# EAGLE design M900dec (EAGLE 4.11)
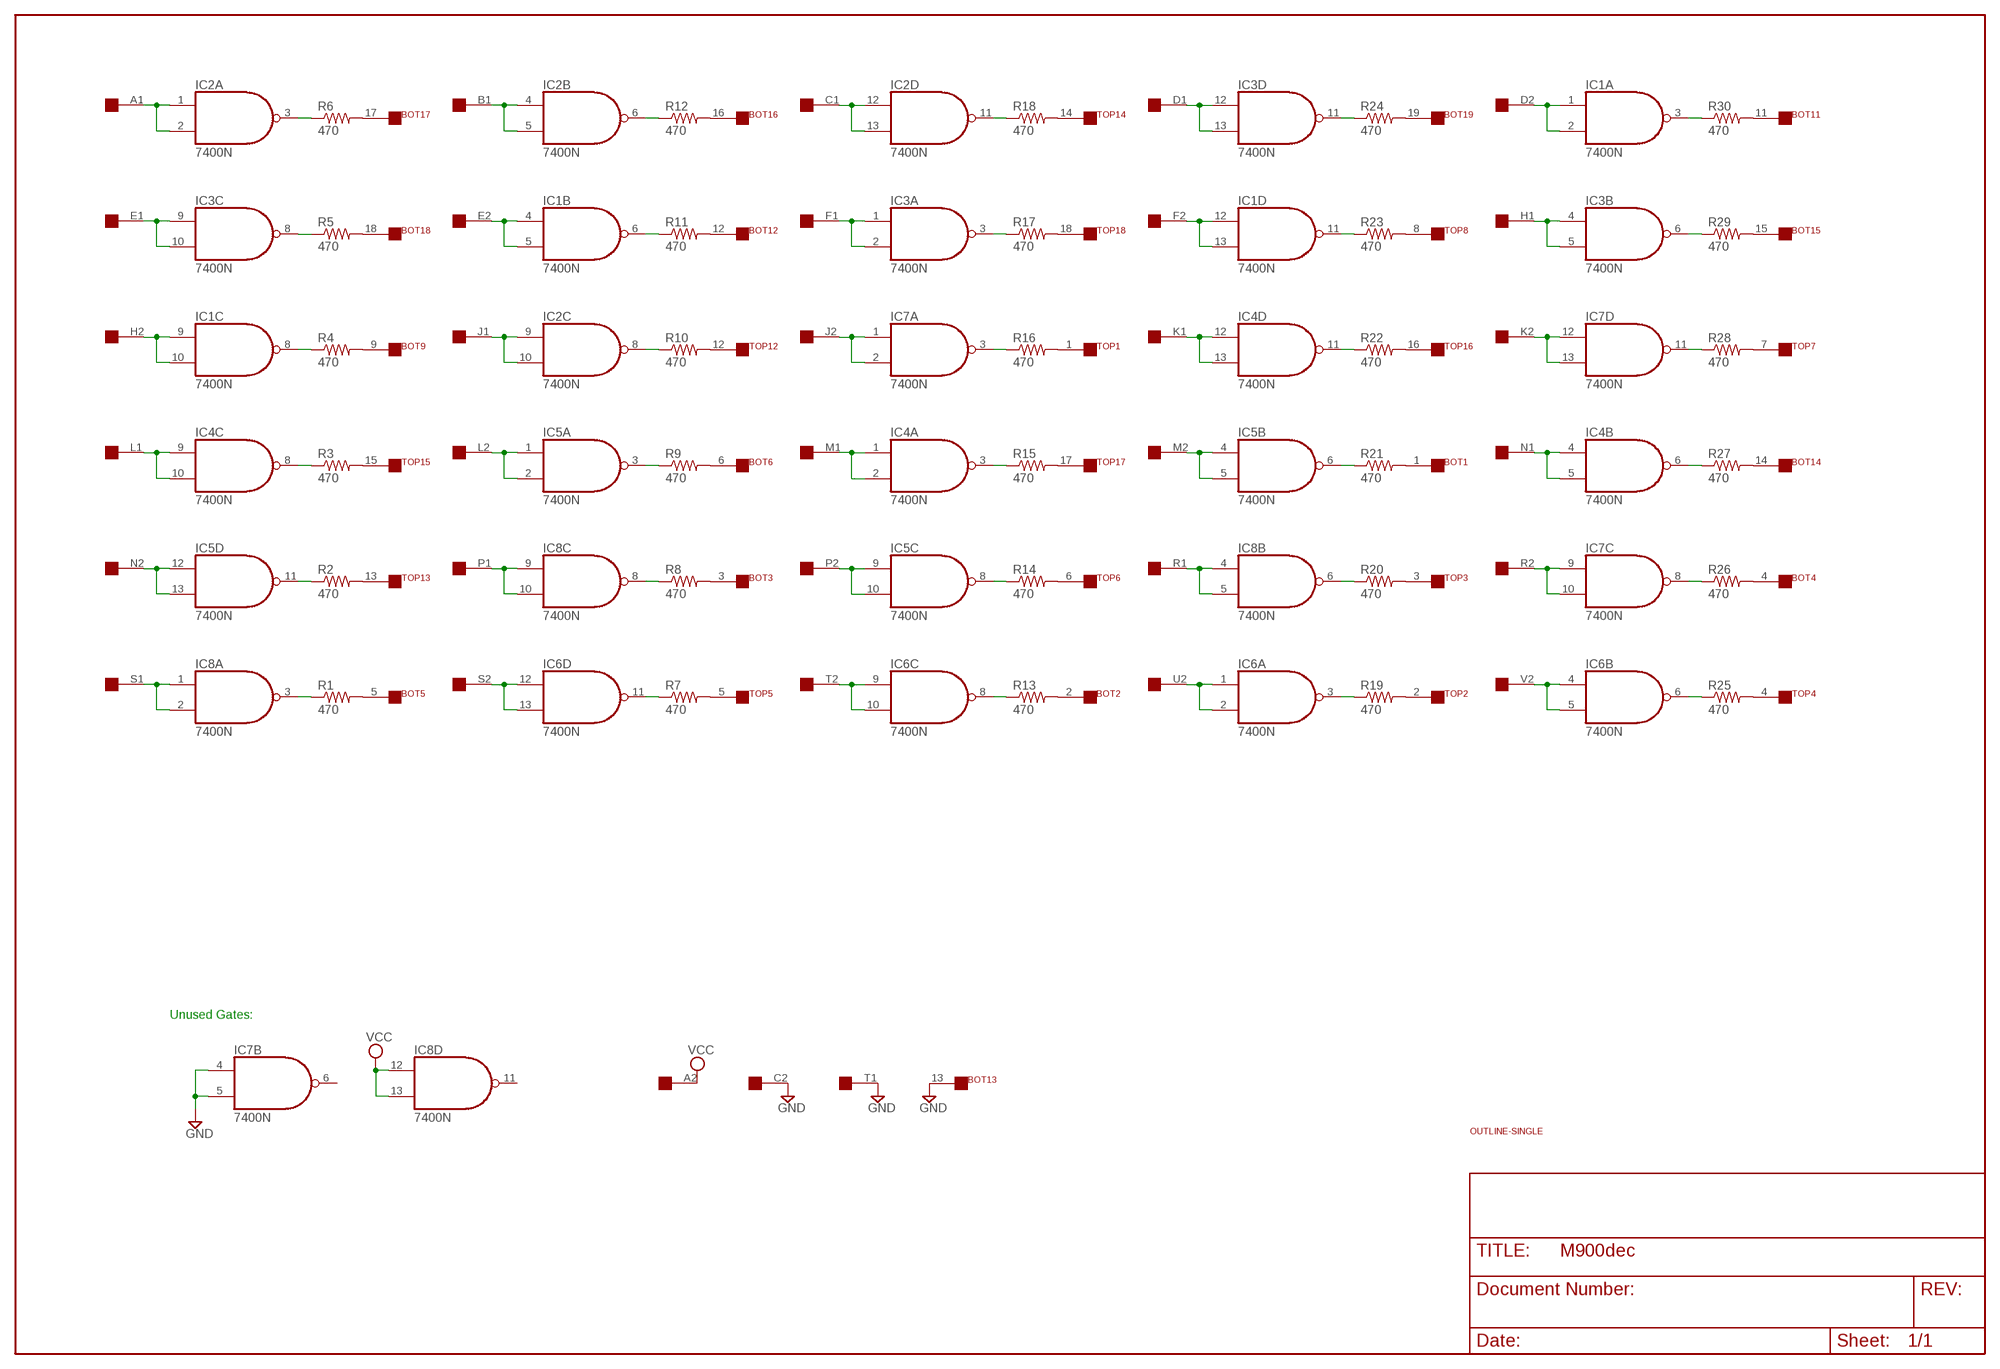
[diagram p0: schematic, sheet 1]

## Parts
BOT  FLEX19  [FLEX19]
EDGE  SINGLE  [EDGE-CON2]
IC1  7400N  [DIL14]
IC2  7400N  [DIL14]
IC3  7400N  [DIL14]
IC4  7400N  [DIL14]
IC5  7400N  [DIL14]
IC6  7400N  [DIL14]
IC7  7400N  [DIL14]
IC8  7400N  [DIL14]
R1  470  R-US_0207/10  [0207/10]
R2  470  R-US_0207/10  [0207/10]
R3  470  R-US_0207/10  [0207/10]
R4  470  R-US_0207/10  [0207/10]
R5  470  R-US_0207/10  [0207/10]
R6  470  R-US_0207/10  [0207/10]
R7  470  R-US_0207/10  [0207/10]
R8  470  R-US_0207/10  [0207/10]
R9  470  R-US_0207/10  [0207/10]
R10  470  R-US_0207/10  [0207/10]
R11  470  R-US_0207/10  [0207/10]
R12  470  R-US_0207/10  [0207/10]
R13  470  R-US_0207/10  [0207/10]
R14  470  R-US_0207/10  [0207/10]
R15  470  R-US_0207/10  [0207/10]
R16  470  R-US_0207/10  [0207/10]
R17  470  R-US_0207/10  [0207/10]
R18  470  R-US_0207/10  [0207/10]
R19  470  R-US_0207/10  [0207/10]
R20  470  R-US_0207/10  [0207/10]
R21  470  R-US_0207/10  [0207/10]
R22  470  R-US_0207/10  [0207/10]
R23  470  R-US_0207/10  [0207/10]
R24  470  R-US_0207/10  [0207/10]
R25  470  R-US_0207/10  [0207/10]
R26  470  R-US_0207/10  [0207/10]
R27  470  R-US_0207/10  [0207/10]
R28  470  R-US_0207/10  [0207/10]
R29  470  R-US_0207/10  [0207/10]
R30  470  R-US_0207/10  [0207/10]
TOP  FLEX19  [FLEX19]
U$2  OUTLINE-SINGLE  [SINGLE]

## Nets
GND: BOT.13 EDGE.C2 EDGE.T1 IC7.4(B:I0) IC7.5(B:I1)
N$1: EDGE.A1 IC2.1(A:I0) IC2.2(A:I1)
N$2: IC2.3(A:O) R6.1
N$3: IC3.8(C:O) R5.1
N$4: IC1.8(C:O) R4.1
N$5: IC4.8(C:O) R3.1
N$6: IC5.11(D:O) R2.1
N$7: EDGE.H2 IC1.9(C:I0) IC1.10(C:I1)
N$8: EDGE.S1 IC8.1(A:I0) IC8.2(A:I1)
N$9: EDGE.N2 IC5.12(D:I0) IC5.13(D:I1)
N$10: EDGE.L1 IC4.9(C:I0) IC4.10(C:I1)
N$11: EDGE.E1 IC3.9(C:I0) IC3.10(C:I1)
N$12: EDGE.P1 IC8.9(C:I0) IC8.10(C:I1)
N$13: EDGE.B1 IC2.4(B:I0) IC2.5(B:I1)
N$14: EDGE.E2 IC1.4(B:I0) IC1.5(B:I1)
N$15: EDGE.J1 IC2.9(C:I0) IC2.10(C:I1)
N$16: EDGE.L2 IC5.1(A:I0) IC5.2(A:I1)
N$17: EDGE.S2 IC6.12(D:I0) IC6.13(D:I1)
N$18: IC8.8(C:O) R8.1
N$19: IC5.3(A:O) R9.1
N$20: IC2.8(C:O) R10.1
N$21: IC1.6(B:O) R11.1
N$22: IC2.6(B:O) R12.1
N$23: IC6.11(D:O) R7.1
N$24: IC8.3(A:O) R1.1
N$25: EDGE.P2 IC5.9(C:I0) IC5.10(C:I1)
N$26: EDGE.C1 IC2.12(D:I0) IC2.13(D:I1)
N$27: EDGE.F1 IC3.1(A:I0) IC3.2(A:I1)
N$28: EDGE.J2 IC7.1(A:I0) IC7.2(A:I1)
N$29: EDGE.M1 IC4.1(A:I0) IC4.2(A:I1)
N$30: EDGE.T2 IC6.9(C:I0) IC6.10(C:I1)
N$31: IC6.8(C:O) R13.1
N$32: IC5.8(C:O) R14.1
N$33: IC4.3(A:O) R15.1
N$34: IC7.3(A:O) R16.1
N$35: IC2.11(D:O) R18.1
N$36: IC3.3(A:O) R17.1
N$37: IC6.3(A:O) R19.1
N$38: IC8.6(B:O) R20.1
N$39: IC5.6(B:O) R21.1
N$40: IC4.11(D:O) R22.1
N$41: IC1.11(D:O) R23.1
N$42: IC3.11(D:O) R24.1
N$43: EDGE.R1 IC8.4(B:I0) IC8.5(B:I1)
N$44: EDGE.F2 IC1.12(D:I0) IC1.13(D:I1)
N$45: EDGE.K1 IC4.12(D:I0) IC4.13(D:I1)
N$46: EDGE.M2 IC5.4(B:I0) IC5.5(B:I1)
N$47: EDGE.U2 IC6.1(A:I0) IC6.2(A:I1)
N$48: EDGE.R2 IC7.9(C:I0) IC7.10(C:I1)
N$49: EDGE.D1 IC3.12(D:I0) IC3.13(D:I1)
N$50: EDGE.D2 IC1.1(A:I0) IC1.2(A:I1)
N$51: EDGE.H1 IC3.4(B:I0) IC3.5(B:I1)
N$52: EDGE.K2 IC7.12(D:I0) IC7.13(D:I1)
N$53: EDGE.N1 IC4.4(B:I0) IC4.5(B:I1)
N$54: EDGE.V2 IC6.4(B:I0) IC6.5(B:I1)
N$55: IC6.6(B:O) R25.1
N$56: IC7.8(C:O) R26.1
N$57: IC4.6(B:O) R27.1
N$58: IC7.11(D:O) R28.1
N$59: IC3.6(B:O) R29.1
N$60: IC1.3(A:O) R30.1
N$61: R17.2 TOP.18
N$62: R15.2 TOP.17
N$63: R22.2 TOP.16
N$64: R3.2 TOP.15
N$65: R18.2 TOP.14
N$66: R2.2 TOP.13
N$67: R10.2 TOP.12
N$68: R23.2 TOP.8
N$69: R28.2 TOP.7
N$70: R14.2 TOP.6
N$71: R7.2 TOP.5
N$72: R25.2 TOP.4
N$73: R20.2 TOP.3
N$74: R19.2 TOP.2
N$75: R16.2 TOP.1
N$76: BOT.15 R29.2
N$77: BOT.3 R8.2
N$78: BOT.1 R21.2
N$79: BOT.2 R13.2
N$80: BOT.4 R26.2
N$81: BOT.5 R1.2
N$82: BOT.19 R24.2
N$83: BOT.18 R5.2
N$84: BOT.17 R6.2
N$85: BOT.16 R12.2
N$86: BOT.14 R27.2
N$87: BOT.12 R11.2
N$88: BOT.9 R4.2
N$89: BOT.6 R9.2
N$90: BOT.11 R30.2
VCC: EDGE.A2 IC8.12(D:I0) IC8.13(D:I1)
Unconnected: BOT.7 BOT.8 BOT.10 EDGE.B2 EDGE.U1 EDGE.V1 IC7.6(B:O) IC8.11(D:O) TOP.9 TOP.10 TOP.11 TOP.19

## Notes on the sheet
- Unused Gates:

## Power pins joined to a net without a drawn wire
GND: IC1.7(P:GND) IC2.7(P:GND) IC3.7(P:GND) IC4.7(P:GND) IC5.7(P:GND) IC6.7(P:GND) IC7.7(P:GND) IC8.7(P:GND)
VCC: IC1.14(P:VCC) IC2.14(P:VCC) IC3.14(P:VCC) IC4.14(P:VCC) IC5.14(P:VCC) IC6.14(P:VCC) IC7.14(P:VCC) IC8.14(P:VCC)

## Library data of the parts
BOT TOP = dec-con:FLEX19
EDGE = dec-con:SINGLE: Single-Height DEC board
IC1-IC8 = 74xx-jameco:74*00: Quad 2-input NAND gate
R1-R30 = rcl:R-US_: RESISTOR, American symbol
U$2 = dec-con:OUTLINE-*: Board outlines for DEC boards.

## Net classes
1 Supply: width 0.762 mm

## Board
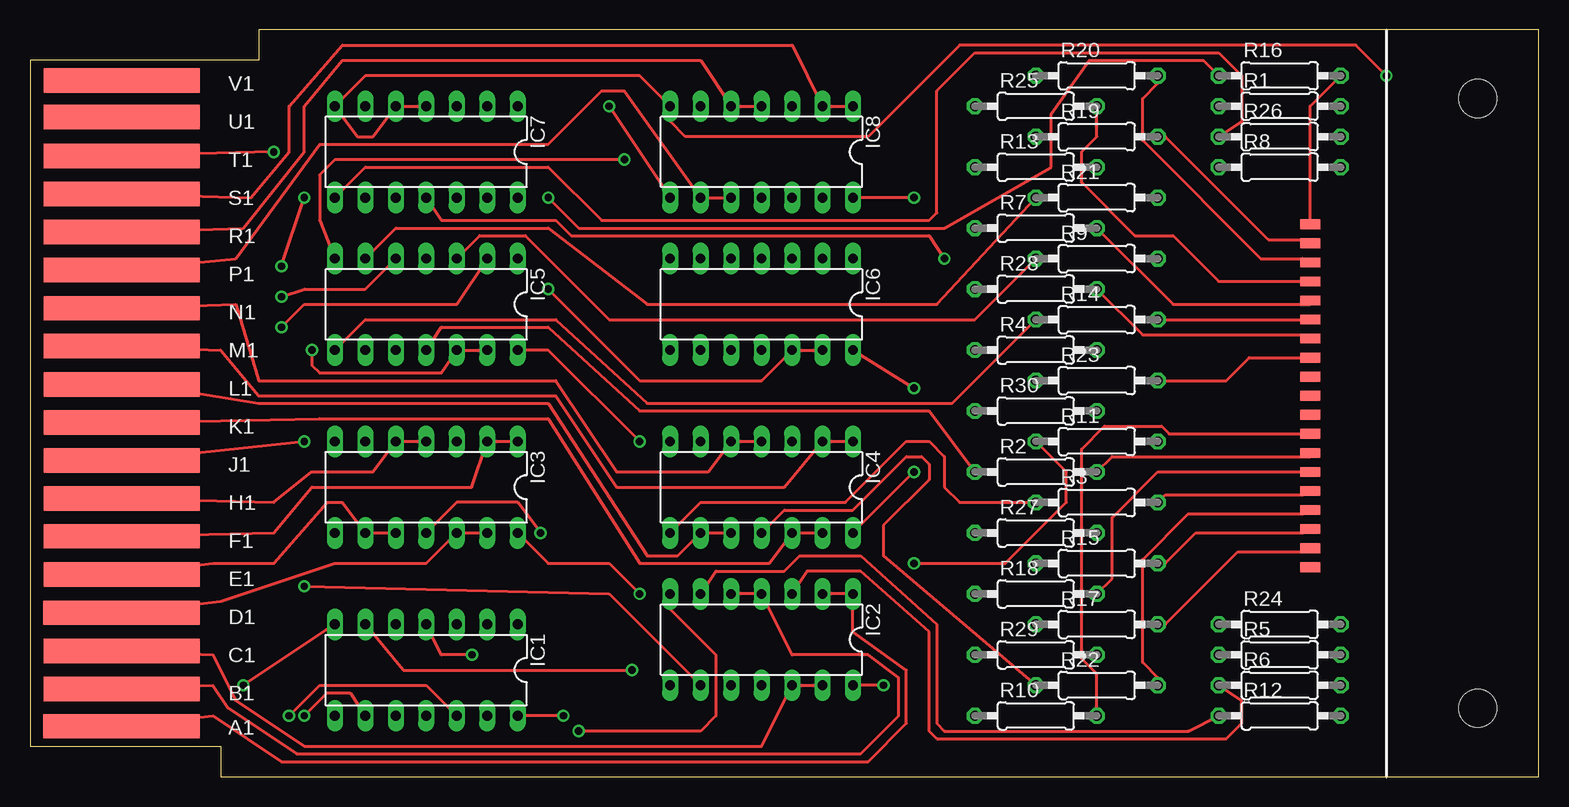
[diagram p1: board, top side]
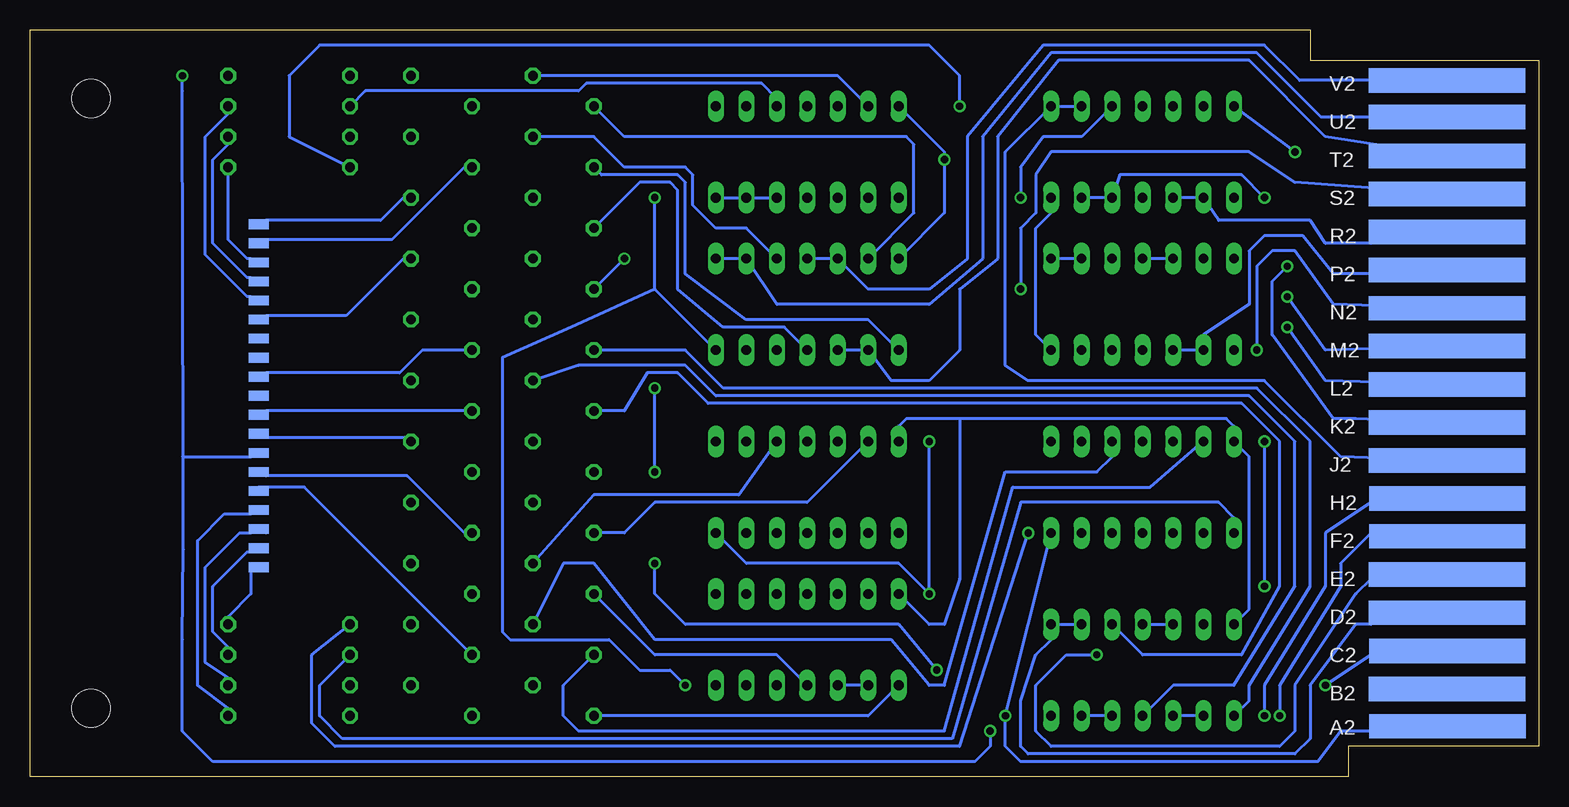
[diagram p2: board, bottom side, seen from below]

Size 125.73 x 62.23 mm. Coordinates in mm from the lower left corner, seen from the top.
Copper layers (1*16): Top 0.035mm / dielectric 1.5mm / Bottom 0.035mm
Design rules "10mils": minimum track width 10mil, minimum drill 24mil, track to track 10mil, track to pad 10mil, pad to pad 10mil, via to via 10mil, smd to smd 10mil, copper to edge 25mil, drill to drill 10mil, minimum pad ring 10mil, minimum via ring 8mil, stop-mask expansion 0mil, vias tented up to drill 0mil, thermal gap 10mil

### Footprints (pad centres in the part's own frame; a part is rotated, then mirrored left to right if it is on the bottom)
FLEX19 = smd 1.676 x 0.813: 1 0,14.287; 2 0,12.7; 3 0,11.113; 4 0,9.525; 5 0,7.938; 6 0,6.35; 7 0,4.763; 8 0,3.175; 9 0,1.587; 10 0,0; 11 0,-1.587; 12 0,-3.175; 13 0,-4.763; 14 0,-6.35; 15 0,-7.938; 16 0,-9.525; 17 0,-11.113; 18 0,-12.7; 19 0,-14.287
EDGE-CON2 = smd 13.017 x 2.032: A1 7.633,4.207; B1 7.639,7.327; C1 7.636,10.489; D1 7.633,13.665; E1 7.642,16.84; F1 7.642,20.041; H1 7.642,23.19; J1 7.642,26.34; K1 7.642,29.515; L1 7.642,32.69; M1 7.642,35.89; N1 7.642,39.04; P1 7.642,42.24; R1 7.642,45.39; S1 7.642,48.565; T1 7.642,51.74; U1 7.642,54.966; V1 7.642,58.026 | smd 13.017 x 2.032 bottom: A2 7.614,4.207; B2 7.642,7.328; C2 7.617,10.49; D2 7.642,13.665; E2 7.642,16.84; F2 7.617,20.041; H2 7.617,23.19; J2 7.642,26.34; K2 7.642,29.515; L2 7.642,32.69; M2 7.642,35.89; N2 7.642,39.04; P2 7.642,42.24; R2 7.642,45.39; S2 7.642,48.565; T2 7.642,51.74; U2 7.642,54.966; V2 7.642,58.026
DIL14 = drill 0.813 long: 1 -7.62,-3.81; 2 -5.08,-3.81; 3 -2.54,-3.81; 4 0,-3.81; 5 2.54,-3.81; 6 5.08,-3.81; 7 7.62,-3.81; 8 7.62,3.81; 9 5.08,3.81; 10 2.54,3.81; 11 0,3.81; 12 -2.54,3.81; 13 -5.08,3.81; 14 -7.62,3.81
0207/10 = drill 0.813 octagon: 1 -5.08,0; 2 5.08,0
SINGLE = hole 3.175: 120.65,56.515; 120.65,5.715

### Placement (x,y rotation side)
BOT  106.68,31.75 0 bottom
EDGE  0,0 0 top
IC1  33.02,8.89 180 top
IC2  60.96,11.43 180 top
IC3  33.02,24.13 180 top
IC4  60.96,24.13 180 top
IC5  33.02,39.37 180 top
IC6  60.96,39.37 180 top
IC7  33.02,52.07 180 top
IC8  60.96,52.07 180 top
R1  104.14,55.88 0 top
R2  83.82,25.4 0 top
R3  88.9,22.86 0 top
R4  83.82,35.56 0 top
R5  104.14,10.16 0 top
R6  104.14,7.62 0 top
R7  83.82,45.72 0 top
R8  104.14,50.8 0 top
R9  88.9,43.18 0 top
R10  83.82,5.08 0 top
R11  88.9,27.94 0 top
R12  104.14,5.08 0 top
R13  83.82,50.8 0 top
R14  88.9,38.1 0 top
R15  88.9,17.78 0 top
R16  104.14,58.42 0 top
R17  88.9,12.7 0 top
R18  83.82,15.24 0 top
R19  88.9,53.34 0 top
R20  88.9,58.42 0 top
R21  88.9,48.26 0 top
R22  88.9,7.62 0 top
R23  88.9,33.02 0 top
R24  104.14,12.7 0 top
R25  83.82,55.88 0 top
R26  104.14,53.34 0 top
R27  83.82,20.32 0 top
R28  83.82,40.64 0 top
R29  83.82,10.16 0 top
R30  83.82,30.48 0 top
TOP  106.68,31.75 0 top
U$2  0,0 0 top

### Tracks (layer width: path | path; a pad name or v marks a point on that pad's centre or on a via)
GND  (via drill 0.61)
  Top 0.254: v17.78,7.62 IC1.7 | v20.32,52.07 EDGE.T1 | IC7.4 IC7.5 28.58,53.34 27.31,53.34 IC7.7 27.94,58.42 50.8,58.42 IC8.7 53.34,54.61 54.61,53.34 69.85,53.34 77.47,60.96 110.49,60.96 v113.03,58.42 | IC5.7 24.13,46.35 24.13,50.16 25.4,51.44 v49.53,51.44 | v45.72,3.81 55.88,3.81 57.15,5.08 57.15,10.16 53.34,13.97 IC2.7
  Bottom 0.254: v17.78,7.62 13.97,10.16 EDGE.C2 | IC1.7 24.13,13.97 24.13,26.67 IC3.7 25.4,29.21 26.04,29.84 48.26,29.84 | IC7.7 v20.32,52.07 | 48.26,29.84 52.71,29.84 53.34,29.21 IC4.7 | IC2.7 50.8,12.7 49.53,12.7 48.26,16.51 48.26,29.84 | IC6.7 49.53,46.99 v49.53,51.44 49.53,52.07 IC8.7 | v45.72,3.81 45.72,2.54 46.99,1.27 110.49,1.27 113.03,3.81 113.03,11.43 112.95,18.95 112.97,26.67 | v113.03,58.42 113.03,57.15 112.97,26.67 | BOT.13 107.32,26.67 113.03,26.67 112.97,26.67
N$1
  Top 0.254: EDGE.A1 15.24,5.08 20.96,1.27 69.85,1.27 73.03,4.45 73.03,8.89 68.58,12.06 IC2.1 IC2.2
N$2
  Top 0.254: IC2.3 64.77,17.14 69.22,17.14 74.93,12.06 74.93,3.81 75.57,3.17 99.7,3.17 100.97,4.45 100.97,6.35 R6.1
N$3
  Bottom 0.254: IC3.8 25.4,21.59 26.67,22.86 43.18,22.86 48.9,3.17 99.7,3.17 101.6,5.08 101.6,7.62 R5.1
N$4
  Bottom 0.254: IC1.8 24.13,6.35 24.13,7.62 19.05,15.88 19.05,27.94 23.5,32.38 67.95,32.38 71.12,35.56 R4.1
N$5
  Top 0.254: IC4.8 55.88,22.86 67.95,22.86 73.03,27.94 74.93,27.94 76.2,26.67 76.2,24.13 77.47,22.86 R3.1
N$6
  Top 0.254: IC5.11 34.29,37.47 43.18,37.47 50.8,30.48 74.93,30.48 R2.1
N$7  (via drill 0.61)
  Top 0.254: v22.86,5.08 24.77,6.99 26.67,6.99 IC1.9
  Bottom 0.254: EDGE.H2 13.97,22.86 17.78,20.32 17.78,15.88 22.86,7.62 v22.86,5.08 | IC1.9 IC1.10
N$8
  Top 0.254: EDGE.S1 18.42,48.26 21.59,52.07 21.59,55.88 26.04,60.96 63.5,60.96 IC8.2 IC8.1
N$9  (via drill 0.61)
  Top 0.254: IC5.13 IC5.12 34.29,33.66 24.13,33.66 23.5,34.29 v23.5,35.56
  Bottom 0.254: EDGE.N2 17.15,39.37 20.32,43.81 22.23,43.81 23.5,42.55 v23.5,35.56
N$10
  Top 0.254: IC4.10 IC4.9 53.98,18.41 51.44,18.41 43.18,31.11 19.05,31.11 7.62,33.02 EDGE.L1
N$11
  Top 0.254: IC3.10 IC3.9 26.04,22.86 24.77,22.86 20.32,17.78 15.24,17.78 EDGE.E1
N$12
  Top 0.254: IC8.10 IC8.9 49.53,57.15 47.63,57.15 43.18,52.7 24.13,52.7 17.15,43.18 EDGE.P1
N$13
  Top 0.254: EDGE.B1 15.24,7.62 16.51,5.71 22.23,1.91 69.22,1.91 72.39,5.08 72.39,8.26 69.85,10.16 63.5,10.16 IC2.4 IC2.5
N$14  (via drill 0.61)
  Top 0.254: v36.83,10.16 34.29,10.16 IC1.4
  Bottom 0.254: EDGE.E2 13.97,16.51 15.24,15.24 20.32,7.62 20.32,3.81 21.59,2.54 40.64,2.54 41.91,3.81 41.91,7.62 39.37,10.16 v36.83,10.16 | IC1.4 IC1.5
N$15  (via drill 0.61)
  Top 0.254: EDGE.J1 v22.86,27.94 | v22.86,15.88 48.26,15.24 IC2.9
  Bottom 0.254: v22.86,27.94 v22.86,15.88 | IC2.9 IC2.10
N$16  (via drill 0.61)
  Top 0.254: v20.96,37.47 22.86,39.37 35.56,39.37 IC5.2
  Bottom 0.254: EDGE.L2 17.78,33.02 v20.96,37.47 | IC5.2 IC5.1
N$17  (via drill 0.61)
  Top 0.254: v43.18,40.64 50.8,33.02 60.96,33.02 IC6.12 IC6.13
  Bottom 0.254: EDGE.S2 20.32,49.53 24.13,52.07 40.64,52.07 41.91,50.16 41.91,46.99 43.18,45.72 v43.18,40.64
N$18  (via drill 0.61)
  Top 0.254: IC8.8 v48.26,55.88
  Bottom 0.254: v48.26,55.88 48.26,58.42 50.8,60.96 101.6,60.96 104.14,58.42 104.14,53.34 R8.1
N$19
  Top 0.254: IC5.3 37.47,45.09 41.28,45.09 48.26,38.1 78.74,38.1 R9.1
N$20
  Bottom 0.254: IC2.8 55.88,5.08 R10.1
N$21  (via drill 0.61)
  Top 0.254: IC1.6 31.12,8.89 v50.17,8.89 | v73.66,17.78 81.28,17.78 86.36,22.86 86.36,25.4 R11.1
  Bottom 0.254: v50.17,8.89 53.34,12.7 71.12,12.7 73.66,15.24 v73.66,17.78
N$22
  Top 0.254: IC2.6 57.15,17.14 62.87,17.14 64.14,18.41 69.22,18.41 75.57,12.7 75.57,4.45 76.2,3.81 96.52,3.81 R12.1
N$23
  Bottom 0.254: IC6.11 62.87,37.47 67.95,37.47 71.76,40.64 71.76,48.9 72.39,49.53 74.93,49.53 R7.1
N$24
  Bottom 0.254: IC8.3 63.5,56.52 64.77,57.78 79.38,57.78 80.01,57.15 97.79,57.15 R1.1
N$25
  Bottom 0.254: EDGE.P2 13.97,41.91 17.15,41.91 19.69,45.09 22.86,45.09 24.13,43.81 24.13,39.37 27.94,36.83 IC5.9 IC5.10
N$26
  Top 0.254: EDGE.C1 15.24,10.16 17.15,6.35 22.86,2.54 60.96,2.54 IC2.12 IC2.13
N$27
  Top 0.254: IC3.1 IC3.2 36.83,24.13 23.5,24.13 20.32,20.32 EDGE.F1
N$28
  Bottom 0.254: EDGE.J2 16.51,26.67 22.86,33.02 42.55,33.02 44.45,34.29 44.45,52.07 IC7.1 IC7.2
N$29
  Top 0.254: EDGE.M1 15.88,35.56 19.05,31.75 43.82,31.75 48.9,24.13 62.87,24.13 IC4.2 IC4.1
N$30
  Bottom 0.254: EDGE.T2 17.78,53.34 24.13,59.69 40.01,59.69 45.09,53.34 45.09,43.18 48.26,40.64 48.26,35.56 50.8,33.02 53.98,33.02 IC6.9 IC6.10
N$31
  Bottom 0.254: IC6.8 55.88,38.1 66.04,38.1 71.12,41.91 71.12,49.53 71.76,50.16 78.11,50.16 R13.1
N$32
  Top 0.254: IC5.8 27.94,38.1 43.82,38.1 51.44,31.11 76.84,31.11 R14.1
N$33
  Bottom 0.254: IC4.3 66.68,23.5 78.74,23.5 R15.1
N$34  (via drill 0.61)
  Top 0.254: v43.18,48.26 45.72,45.72 76.2,45.72 85.09,50.8 85.09,55.24 88.27,59.69 97.79,59.69 R16.1
  Bottom 0.254: IC7.3 38.1,53.34 41.28,53.34 43.18,50.8 v43.18,48.26
N$35
  Bottom 0.254: IC2.11 63.5,10.16 73.66,10.16 R18.1
N$36
  Bottom 0.254: IC3.3 35.56,26.67 36.83,25.4 44.45,25.4 49.53,7.62 50.8,7.62 53.98,11.43 73.66,11.43 78.74,17.78 81.28,17.78 R17.1
N$37
  Bottom 0.254: IC6.3 66.04,45.72 68.58,45.72 70.49,47.62 70.49,50.16 71.12,50.8 76.2,50.8 78.74,53.34 R19.1
N$38
  Bottom 0.254: IC8.6 58.42,58.42 R20.1
N$39
  Top 0.254: IC5.6 30.48,45.72 43.18,45.72 51.44,39.37 75.57,39.37 R21.1
N$40
  Top 0.254: IC4.11 62.87,22.23 68.58,22.23 73.03,26.67 74.3,26.67 74.93,26.04 74.93,24.77 71.12,20.95 71.12,18.41 R22.1
N$41
  Bottom 0.254: IC1.11 30.48,7.62 25.4,7.62 20.32,15.88 20.32,27.94 24.13,31.75 68.58,31.75 71.12,34.29 80.01,34.29 R23.1
N$42  (via drill 0.61)
  Top 0.254: IC3.11 35.56,22.86 40.64,22.86 v42.55,20.32
  Bottom 0.254: v42.55,20.32 48.26,2.54 100.33,2.54 102.24,4.45 102.24,10.16 R24.1
N$43
  Top 0.254: EDGE.R1 17.78,45.72 22.86,52.07 22.86,55.88 26.04,59.69 55.88,59.69 IC8.5 IC8.4
N$44  (via drill 0.61)
  Top 0.254: IC1.12 33.02,7.62 24.13,7.62 v21.59,5.08
  Bottom 0.254: EDGE.F2 13.97,20.32 16.51,17.78 16.51,15.88 21.59,7.62 v21.59,5.08 | IC1.12 IC1.13
N$45
  Top 0.254: EDGE.K1 24.13,29.84 43.18,29.84 50.8,17.78 61.6,17.78 IC4.12 IC4.13
N$46  (via drill 0.61)
  Top 0.254: v20.96,40.01 22.86,40.64 27.94,40.64 IC5.5
  Bottom 0.254: EDGE.M2 17.78,35.56 v20.96,40.01 | IC5.5 IC5.4
N$47
  Bottom 0.254: EDGE.U2 18.14,54.97 23.5,60.33 40.64,60.33 46.36,53.34 46.36,43.18 50.8,39.37 63.5,39.37 IC6.2 IC6.1
N$48
  Bottom 0.254: EDGE.R2 13.97,44.45 17.78,44.45 19.05,46.35 26.67,46.35 IC7.9 IC7.10
N$49
  Top 0.254: IC3.13 IC3.12 33.02,17.78 25.4,17.78 15.88,14.61 EDGE.D1
N$50
  Bottom 0.254: EDGE.D2 13.97,12.7 15.24,12.7 19.05,7.62 19.05,3.17 20.32,1.91 42.55,1.91 43.18,2.54 43.18,6.35 41.91,10.16 40.64,11.43 IC1.1 IC1.2
N$51
  Top 0.254: EDGE.H1 20.32,22.86 23.5,25.4 28.58,25.4 IC3.5 IC3.4
N$52  (via drill 0.61)
  Top 0.254: v20.96,42.55 v22.86,48.26
  Bottom 0.254: IC7.13 IC7.12 34.93,50.16 24.77,50.16 v22.86,48.26 | EDGE.K2 15.24,29.84 17.15,29.84 22.23,36.83 22.23,41.27 v20.96,42.55
N$53
  Top 0.254: EDGE.N1 17.15,39.37 19.05,33.02 43.82,33.02 48.9,25.4 56.52,25.4 IC4.5 IC4.4
N$54
  Bottom 0.254: EDGE.V2 19.93,58.03 22.86,60.96 41.28,60.96 47.63,53.34 47.63,43.18 50.8,40.64 55.88,40.64 IC6.5 IC6.4
N$55
  Bottom 0.254: IC6.6 52.07,46.99 52.07,52.7 52.71,53.34 76.2,53.34 R25.1
N$56
  Top 0.254: IC7.8 27.94,50.8 43.18,50.8 47.63,46.35 74.93,46.35 75.57,46.99 75.57,57.15 78.74,60.33 99.06,60.33 100.97,58.42 100.97,54.61 R26.1
N$57
  Bottom 0.254: IC4.6 60.96,22.86 73.66,22.86 76.2,20.32 R27.1
N$58  (via drill 0.61)
  Top 0.254: IC7.11 34.29,46.35 43.82,46.35 45.09,45.09 74.93,45.09 v76.2,43.18
  Bottom 0.254: v76.2,43.18 R28.1
N$59
  Bottom 0.254: IC3.6 32.39,24.13 43.82,24.13 49.53,3.81 80.01,3.81 81.28,5.08 81.28,7.62 R29.1
N$60
  Bottom 0.254: IC1.3 33.02,10.16 24.77,10.16 21.59,15.88 21.59,27.94 24.77,31.11 69.22,31.11 71.76,33.66 74.3,33.66 76.2,30.48 R30.1
N$61
  Top 0.254: TOP.18 106.05,18.73 100.65,18.73 94.62,12.7 R17.2
N$62
  Top 0.254: TOP.17 106.05,20.32 97.16,20.32 94.62,17.78 R15.2
N$63
  Top 0.254: TOP.16 106.05,21.91 96.52,21.91 92.71,18.1 92.71,9.53 93.98,8.26 R22.2
N$64
  Top 0.254: TOP.15 106.05,23.5 94.62,23.5 R3.2
N$65
  Top 0.254: TOP.14 93.98,25.4 90.17,21.59 90.17,16.51 R18.2
N$66
  Top 0.254: R2.2 90.17,26.67 106.68,26.67 TOP.13
N$67
  Top 0.254: R10.2 88.9,8.57 87.63,9.84 87.63,27.3 89.54,29.21 94.3,29.21 94.93,28.57 TOP.12
N$68
  Top 0.254: TOP.8 101.6,34.92 99.7,33.02 R23.2
N$69
  Top 0.254: R28.2 92.71,36.83 106.68,36.83 TOP.7
N$70
  Top 0.254: R14.2 TOP.6
N$71
  Top 0.254: R7.2 95.25,39.37 106.68,39.37 TOP.5
N$72
  Top 0.254: TOP.4 99.06,41.27 95.25,45.09 92.08,45.09 87.63,49.53 87.63,52.07 88.9,53.34 R25.2
N$73
  Top 0.254: TOP.3 106.05,43.18 102.55,43.18 92.71,53.02 92.71,56.52 93.98,57.78 R20.2
N$74
  Top 0.254: TOP.2 106.05,44.77 103.19,44.77 94.62,53.34 R19.2
N$75
  Top 0.254: R16.2 106.68,55.88 TOP.1 106.68,45.72
N$76
  Bottom 0.254: R29.2 102.87,24.13 106.68,24.13 BOT.15
N$77
  Bottom 0.254: BOT.3 107.32,43.18 107.63,43.18 109.22,44.77 R8.2
N$78
  Bottom 0.254: BOT.1 106.05,46.35 96.52,46.35 94.62,48.26 R21.2
N$79
  Bottom 0.254: BOT.2 106.05,44.77 95.57,44.77 89.54,50.8 R13.2
N$80
  Bottom 0.254: BOT.4 107.32,41.59 107.63,41.59 110.49,44.45 110.49,51.44 109.22,52.7 R26.2
N$81
  Bottom 0.254: BOT.5 107.32,40.01 107.63,40.01 111.13,43.5 111.13,53.34 109.22,55.24 R1.2
N$82
  Bottom 0.254: BOT.19 107.32,17.14 107.32,15.24 109.22,13.34 R24.2
N$83
  Bottom 0.254: BOT.18 107.32,18.73 107.63,18.73 110.49,15.88 110.49,12.06 109.22,10.79 R5.2
N$84
  Bottom 0.254: 106.05,20.32 BOT.17 107.32,20.32 108.27,20.32 111.13,17.46 111.13,9.53 109.22,8.26 R6.2
N$85
  Bottom 0.254: R12.2 109.22,5.71 111.76,7.62 111.76,19.68 109.54,21.91 107.32,21.91 BOT.16
N$86
  Bottom 0.254: BOT.14 106.05,25.08 94.3,25.08 89.54,20.32 R27.2
N$87
  Bottom 0.254: BOT.12 106.05,28.26 94.3,28.26 R11.2
N$88
  Bottom 0.254: BOT.9 106.05,33.66 94.93,33.66 93.03,35.56 R4.2
N$89
  Bottom 0.254: BOT.6 106.05,38.42 99.38,38.42 94.62,43.18 R9.2
N$90
  Bottom 0.254: BOT.11 106.05,30.48 R30.2
VCC  (via drill 0.61)
  Top 0.254: v44.45,5.08 IC1.14 | IC3.14 43.18,17.78 48.26,17.78 v50.8,15.24 | v50.8,27.94 43.18,35.56 IC5.14 | IC4.14 v73.66,25.4 | v73.66,32.38 IC6.14 | v71.12,7.62 IC2.14 | v73.66,48.26 IC8.14
  Bottom 0.254: EDGE.A2 13.97,3.81 16.51,3.81 18.42,1.27 43.18,1.27 44.45,2.54 v44.45,5.08 IC3.14 | IC5.14 41.91,36.83 41.91,45.72 40.64,46.99 IC7.14 | IC4.14 66.04,17.78 53.34,17.78 v50.8,15.24 v50.8,27.94 | v73.66,25.4 v73.66,32.38 | IC8.14 IC8.13 IC8.12 | v71.12,7.62 72.39,8.89 74.93,8.89 77.47,11.43 85.73,11.43 86.36,12.06 86.36,34.92 80.65,37.47 73.66,40.64 | 73.66,40.64 v73.66,48.26 | IC6.14 73.66,40.64

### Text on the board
tPlace: Trace layout does not match DEC's!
